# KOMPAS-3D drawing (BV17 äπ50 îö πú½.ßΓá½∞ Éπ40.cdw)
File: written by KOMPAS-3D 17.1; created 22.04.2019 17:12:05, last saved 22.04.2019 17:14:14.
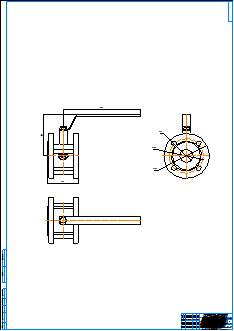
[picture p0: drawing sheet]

Sheet 1: A0, portrait

Title block, sheet 1: name: BV17 Ду50 МФ угл.сталь Ру40; material: Внимание! Данный продукт является объектом авторского права ООО «Торговый Дом АДЛ». / Запрещается изменение, копирование, распространение / (в том числе путем копирования на другие сайты и ресурсы в Интернете) / или любое иное использование информации и объектов без предварительного / согласия правообладателя (ООО «Торговый Дом АДЛ»).; mass: 8,25; sheets: 1; organisation: ООО "Торговый дом АДЛ"; sheet format: A0; stored path: \\adlc.lan\data\АДЛ_ПКД\3D-модели\ADL production\Краны шаровые серии BV\BV17 МФ угл.сталь Ру40\KOMPAS 2D\BV17 Ду50 МФ угл.сталь Ру40.cdw

Views: Вид 1, Проекционный вид 2, Проекционный вид 3
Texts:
  user
Dimensions and other numbers on the sheet: 280; 148; 113; 125; 50; 165; 1:1; 1; 8,25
